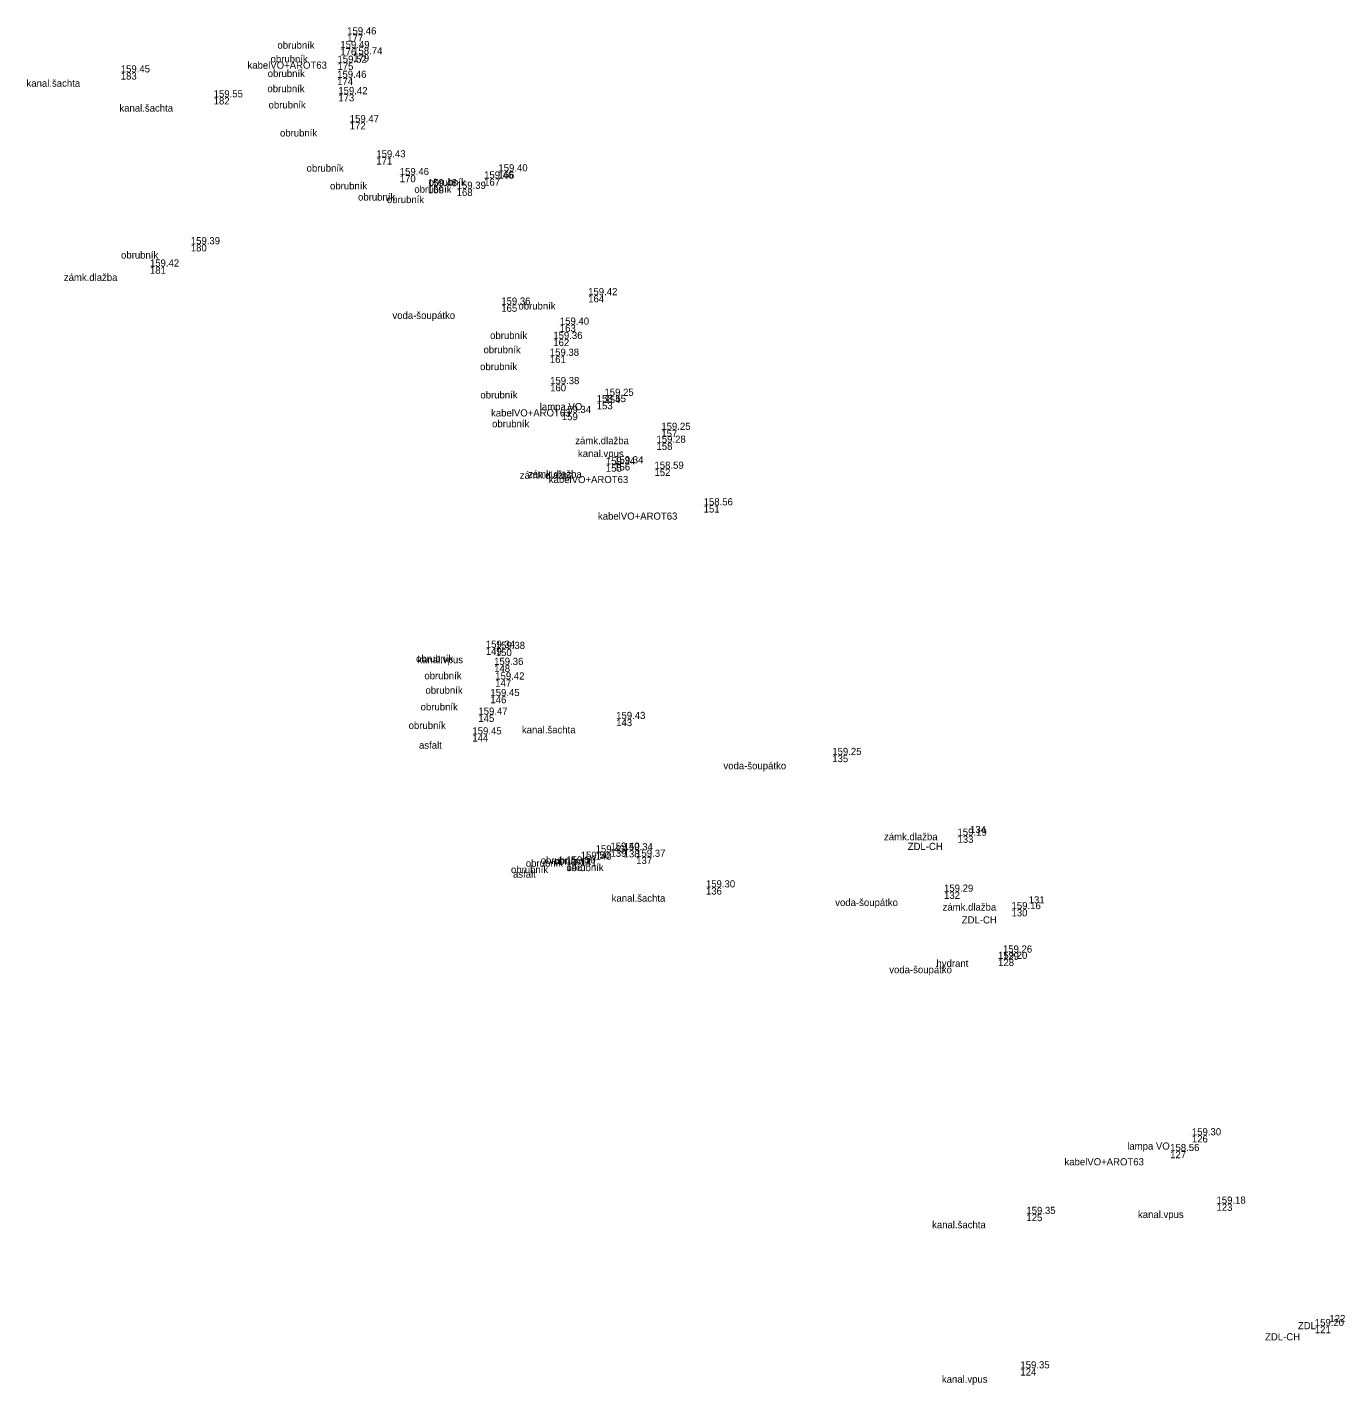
# Model space of a CAD drawing. Extents: x -583304 to -583163, y -1211038 to -1210841.
# Drawn here: x -583271.15 to -583225.05, y -1210935.27 to -1210887.79 of the extents above; entities that cross this region are included whole.
import ezdxf

# ---------------------------------------------------------------- set-up
doc = ezdxf.new("R2010")
doc.units = 0
for name, color, linetype in [('Vrstva 10', 7, 'Continuous'), ('Vrstva 7', 7, 'Continuous'), ('Vrstva 8', 7, 'Continuous'), ('Vrstva 9', 7, 'Continuous')]:
    doc.layers.add(name, color=color, linetype=linetype)

msp = doc.modelspace()

# ---------------------------------------------------------------- linework, layer by layer
at = {"layer": 'Vrstva 7'}
for p, q in [((-583259.95, -1210888.04), (-583259.95, -1210888.04)), ((-583260.19, -1210888.52), (-583260.19, -1210888.52)), ((-583259.74, -1210888.74), (-583259.74, -1210888.74)), ((-583260.29, -1210889.03), (-583260.29, -1210889.03)), ((-583267.87, -1210889.37), (-583267.87, -1210889.37)), ((-583260.3, -1210889.56), (-583260.3, -1210889.56)), ((-583264.62, -1210890.24), (-583264.62, -1210890.24)), ((-583260.26, -1210890.13), (-583260.26, -1210890.13)), ((-583259.86, -1210891.11), (-583259.86, -1210891.11)), ((-583258.93, -1210892.34), (-583258.93, -1210892.34)), ((-583258.11, -1210892.96), (-583258.11, -1210892.96)), ((-583255.16, -1210893.08), (-583255.16, -1210893.08)), ((-583254.66, -1210892.83), (-583254.66, -1210892.83)), ((-583257.13, -1210893.35), (-583257.13, -1210893.35)), ((-583256.12, -1210893.44), (-583256.12, -1210893.44)), ((-583265.42, -1210895.38), (-583265.42, -1210895.38)), ((-583266.85, -1210896.16), (-583266.85, -1210896.16)), ((-583251.52, -1210897.16), (-583251.52, -1210897.16)), ((-583254.56, -1210897.49), (-583254.56, -1210897.49)), ((-583252.51, -1210898.19), (-583252.51, -1210898.19)), ((-583252.74, -1210898.69), (-583252.74, -1210898.69)), ((-583252.86, -1210899.28), (-583252.86, -1210899.28)), ((-583252.85, -1210900.27), (-583252.85, -1210900.27)), ((-583250.95, -1210900.68), (-583250.95, -1210900.68)), ((-583251.22, -1210900.9), (-583251.22, -1210900.9)), ((-583252.44, -1210901.28), (-583252.44, -1210901.28)), ((-583248.96, -1210901.87), (-583248.96, -1210901.87)), ((-583249.13, -1210902.32), (-583249.13, -1210902.32)), ((-583250.9, -1210903.08), (-583250.9, -1210903.08)), ((-583250.61, -1210903.04), (-583250.61, -1210903.04)), ((-583249.2, -1210903.23), (-583249.2, -1210903.23)), ((-583247.48, -1210904.51), (-583247.48, -1210904.51)), ((-583255.1, -1210909.49), (-583255.1, -1210909.49)), ((-583254.75, -1210909.53), (-583254.75, -1210909.53)), ((-583254.81, -1210910.09), (-583254.81, -1210910.09)), ((-583254.77, -1210910.6), (-583254.77, -1210910.6)), ((-583254.94, -1210911.18), (-583254.94, -1210911.18)), ((-583255.36, -1210911.83), (-583255.36, -1210911.83)), ((-583250.54, -1210911.98), (-583250.54, -1210911.98)), ((-583255.57, -1210912.52), (-583255.57, -1210912.52)), ((-583242.98, -1210913.24), (-583242.98, -1210913.24)), ((-583238.16, -1210915.72), (-583238.16, -1210915.72)), ((-583238.6, -1210916.06), (-583238.6, -1210916.06)), ((-583251.26, -1210916.65), (-583251.26, -1210916.65)), ((-583250.74, -1210916.55), (-583250.74, -1210916.55)), ((-583250.28, -1210916.57), (-583250.28, -1210916.57)), ((-583249.84, -1210916.8), (-583249.84, -1210916.8)), ((-583252.28, -1210917.03), (-583252.28, -1210917.03)), ((-583251.78, -1210916.87), (-583251.78, -1210916.87)), ((-583247.4, -1210917.87), (-583247.4, -1210917.87)), ((-583239.07, -1210918.02), (-583239.07, -1210918.02)), ((-583236.11, -1210918.18), (-583236.11, -1210918.18)), ((-583236.71, -1210918.63), (-583236.71, -1210918.63)), ((-583237.01, -1210920.15), (-583237.01, -1210920.15)), ((-583237.18, -1210920.37), (-583237.18, -1210920.37)), ((-583230.4, -1210926.54), (-583230.4, -1210926.54)), ((-583231.16, -1210927.09), (-583231.16, -1210927.09)), ((-583229.54, -1210928.93), (-583229.54, -1210928.93)), ((-583236.19, -1210929.29), (-583236.19, -1210929.29)), ((-583225.59, -1210932.82), (-583225.59, -1210932.82)), ((-583226.1, -1210933.21), (-583226.1, -1210933.21)), ((-583236.4, -1210934.69), (-583236.4, -1210934.69))]:
    msp.add_line(p, q, dxfattribs=at)

# ---------------------------------------------------------------- texts
at = {"layer": 'Vrstva 10'}
for s, p in [('obrubník', (-583262.39, -1210888.54)), ('obrubník', (-583262.63, -1210889.02)), ('kabelVO+AROT63', (-583263.437, -1210889.24)), ('obrubník', (-583262.73, -1210889.53)), ('kanal.šachta', (-583271.168, -1210889.87)), ('obrubník', (-583262.74, -1210890.06)), ('kanal.šachta', (-583267.918, -1210890.74)), ('obrubník', (-583262.7, -1210890.63)), ('obrubník', (-583262.3, -1210891.61)), ('obrubník', (-583261.37, -1210892.84)), ('obrubník', (-583257.1, -1210893.33)), ('obrubník', (-583260.55, -1210893.46)), ('obrubník', (-583259.57, -1210893.85)), ('obrubník', (-583257.6, -1210893.58)), ('obrubník', (-583258.56, -1210893.94)), ('obrubník', (-583267.86, -1210895.88)), ('zámk.dlažba', (-583269.862, -1210896.66)), ('voda-šoupátko', (-583258.367, -1210897.99)), ('obrubník', (-583253.96, -1210897.66)), ('obrubník', (-583254.95, -1210898.69)), ('obrubník', (-583255.18, -1210899.19)), ('obrubník', (-583255.3, -1210899.78)), ('obrubník', (-583255.29, -1210900.77)), ('kabelVO+AROT63', (-583254.917, -1210901.4)), ('lampa VO', (-583253.212, -1210901.18)), ('obrubník', (-583254.88, -1210901.78)), ('zámk.dlažba', (-583251.972, -1210902.37)), ('kanal.vpus', (-583251.876, -1210902.82)), ('zámk.dlažba', (-583253.912, -1210903.58)), ('zámk.dlažba', (-583253.622, -1210903.54)), ('kabelVO+AROT63', (-583252.897, -1210903.73)), ('kabelVO+AROT63', (-583251.177, -1210905.01)), ('obrubník', (-583257.54, -1210909.99)), ('kanal.vpus', (-583257.496, -1210910.03)), ('obrubník', (-583257.25, -1210910.59)), ('obrubník', (-583257.21, -1210911.1)), ('obrubník', (-583257.38, -1210911.68)), ('obrubník', (-583257.8, -1210912.33)), ('kanal.šachta', (-583253.838, -1210912.48)), ('asfalt', (-583257.438, -1210913.02)), ('voda-šoupátko', (-583246.787, -1210913.74)), ('zámk.dlažba', (-583241.172, -1210916.22)), ('ZDL-CH', (-583240.34, -1210916.56)), ('obrubník', (-583253.18, -1210917.05)), ('obrubník', (-583252.72, -1210917.07)), ('obrubník', (-583254.22, -1210917.37)), ('asfalt', (-583254.148, -1210917.53)), ('obrubník', (-583253.7, -1210917.15)), ('obrubník', (-583252.28, -1210917.3)), ('kanal.šachta', (-583250.698, -1210918.37)), ('voda-šoupátko', (-583242.877, -1210918.52)), ('zámk.dlažba', (-583239.122, -1210918.68)), ('ZDL-CH', (-583238.45, -1210919.13)), ('voda-šoupátko', (-583240.987, -1210920.87)), ('hydrant', (-583239.336, -1210920.65)), ('lampa VO', (-583232.662, -1210927.04)), ('kabelVO+AROT63', (-583234.857, -1210927.59)), ('kanal.vpus', (-583232.286, -1210929.43)), ('kanal.šachta', (-583239.488, -1210929.79)), ('ZDL-CH', (-583227.84, -1210933.71)), ('ZDL', (-583226.692, -1210933.32)), ('kanal.vpus', (-583239.146, -1210935.19))]:
    msp.add_text(s, height=0.25, dxfattribs=at).set_placement(p)
at = {"layer": 'Vrstva 8'}
for s, p in [('177', (-583259.95, -1210888.29)), ('176', (-583260.19, -1210888.77)), ('179', (-583259.74, -1210888.99)), ('175', (-583260.29, -1210889.28)), ('183', (-583267.87, -1210889.62)), ('174', (-583260.3, -1210889.81)), ('182', (-583264.62, -1210890.49)), ('173', (-583260.26, -1210890.38)), ('172', (-583259.86, -1210891.36)), ('171', (-583258.93, -1210892.59)), ('170', (-583258.11, -1210893.21)), ('167', (-583255.16, -1210893.33)), ('166', (-583254.66, -1210893.08)), ('169', (-583257.13, -1210893.6)), ('168', (-583256.12, -1210893.69)), ('180', (-583265.42, -1210895.63)), ('181', (-583266.85, -1210896.41)), ('164', (-583251.52, -1210897.41)), ('165', (-583254.56, -1210897.74)), ('163', (-583252.51, -1210898.44)), ('162', (-583252.74, -1210898.94)), ('161', (-583252.86, -1210899.53)), ('160', (-583252.85, -1210900.52)), ('154', (-583250.95, -1210900.93)), ('153', (-583251.22, -1210901.15)), ('159', (-583252.44, -1210901.53)), ('157', (-583248.96, -1210902.12)), ('158', (-583249.13, -1210902.57)), ('155', (-583250.9, -1210903.33)), ('156', (-583250.61, -1210903.29)), ('152', (-583249.2, -1210903.48)), ('151', (-583247.48, -1210904.76)), ('149', (-583255.1, -1210909.74)), ('150', (-583254.75, -1210909.78)), ('148', (-583254.81, -1210910.34)), ('147', (-583254.77, -1210910.85)), ('146', (-583254.94, -1210911.43)), ('145', (-583255.36, -1210912.08)), ('143', (-583250.54, -1210912.23)), ('144', (-583255.57, -1210912.77)), ('135', (-583242.98, -1210913.49)), ('134', (-583238.16, -1210915.97)), ('133', (-583238.6, -1210916.31)), ('140', (-583251.26, -1210916.9)), ('139', (-583250.74, -1210916.8)), ('138', (-583250.28, -1210916.82)), ('137', (-583249.84, -1210917.05)), ('142', (-583252.28, -1210917.28)), ('141', (-583251.78, -1210917.12)), ('136', (-583247.4, -1210918.12)), ('132', (-583239.07, -1210918.27)), ('131', (-583236.11, -1210918.43)), ('130', (-583236.71, -1210918.88)), ('129', (-583237.01, -1210920.4)), ('128', (-583237.18, -1210920.62)), ('126', (-583230.4, -1210926.79)), ('127', (-583231.16, -1210927.34)), ('123', (-583229.54, -1210929.18)), ('125', (-583236.19, -1210929.54)), ('122', (-583225.59, -1210933.07)), ('121', (-583226.1, -1210933.46)), ('124', (-583236.4, -1210934.94))]:
    msp.add_text(s, height=0.25, dxfattribs=at).set_placement(p)
at = {"layer": 'Vrstva 9'}
for s, p in [('159.46 ', (-583259.95, -1210888.04)), ('159.49 ', (-583260.19, -1210888.52)), ('159.52 ', (-583260.29, -1210889.03)), ('158.74 ', (-583259.74, -1210888.74)), ('159.45 ', (-583267.87, -1210889.37)), ('159.46 ', (-583260.3, -1210889.56)), ('159.55 ', (-583264.62, -1210890.24)), ('159.42 ', (-583260.26, -1210890.13)), ('159.47 ', (-583259.86, -1210891.11)), ('159.43 ', (-583258.93, -1210892.34)), ('159.40 ', (-583254.66, -1210892.83)), ('159.46 ', (-583258.11, -1210892.96)), ('159.48 ', (-583257.13, -1210893.35)), ('159.46 ', (-583255.16, -1210893.08)), ('159.39 ', (-583256.12, -1210893.44)), ('159.39 ', (-583265.42, -1210895.38)), ('159.42 ', (-583266.85, -1210896.16)), ('159.42 ', (-583251.52, -1210897.16)), ('159.36 ', (-583254.56, -1210897.49)), ('159.40 ', (-583252.51, -1210898.19)), ('159.36 ', (-583252.74, -1210898.69)), ('159.38 ', (-583252.86, -1210899.28)), ('159.38 ', (-583252.85, -1210900.27)), ('158.55 ', (-583251.22, -1210900.9)), ('159.25 ', (-583250.95, -1210900.68)), ('159.34 ', (-583252.44, -1210901.28)), ('159.25 ', (-583248.96, -1210901.87)), ('159.28 ', (-583249.13, -1210902.32)), ('159.34 ', (-583250.9, -1210903.08)), ('159.34 ', (-583250.61, -1210903.04)), ('158.59 ', (-583249.2, -1210903.23)), ('158.56 ', (-583247.48, -1210904.51)), ('159.34 ', (-583255.1, -1210909.49)), ('159.38 ', (-583254.75, -1210909.53)), ('159.36 ', (-583254.81, -1210910.09)), ('159.42 ', (-583254.77, -1210910.6)), ('159.45 ', (-583254.94, -1210911.18)), ('159.47 ', (-583255.36, -1210911.83)), ('159.43 ', (-583250.54, -1210911.98)), ('159.45 ', (-583255.57, -1210912.52)), ('159.25 ', (-583242.98, -1210913.24)), ('159.19 ', (-583238.6, -1210916.06)), ('159.40 ', (-583250.74, -1210916.55)), ('159.34 ', (-583250.28, -1210916.57)), ('159.50 ', (-583252.28, -1210917.03)), ('159.50 ', (-583251.78, -1210916.87)), ('159.43 ', (-583251.26, -1210916.65)), ('159.37 ', (-583249.84, -1210916.8)), ('159.30 ', (-583247.4, -1210917.87)), ('159.29 ', (-583239.07, -1210918.02)), ('159.16 ', (-583236.71, -1210918.63)), ('159.20 ', (-583237.18, -1210920.37)), ('159.26 ', (-583237.01, -1210920.15)), ('159.30 ', (-583230.4, -1210926.54)), ('158.56 ', (-583231.16, -1210927.09)), ('159.18 ', (-583229.54, -1210928.93)), ('159.35 ', (-583236.19, -1210929.29)), ('159.20 ', (-583226.1, -1210933.21)), ('159.35 ', (-583236.4, -1210934.69))]:
    msp.add_text(s, height=0.25, dxfattribs=at).set_placement(p)

doc.saveas('drawing.dxf')
